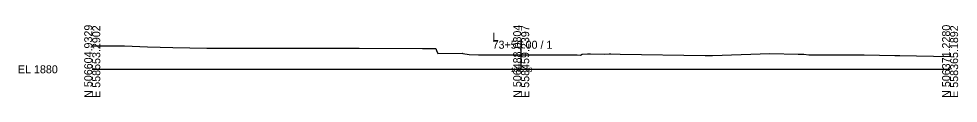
# Model space of a CAD drawing. Extents: x -26 to 4603, y -10 to 4703.
# Drawn here: x 2974.3 to 3302.8, y 1465.3 to 1490.5 of the extents above; entities that cross this region are included whole.
import ezdxf

# ---------------------------------------------------------------- set-up
doc = ezdxf.new("R2010")
doc.units = 0
for name, color, linetype in [('Default', 7, 'Continuous'), ('Exist Cross Section Cell', 7, 'Continuous'), ('Exist XS Ground Line', 7, 'Continuous'), ('Prop XS SS Elevation Text', 7, 'Continuous')]:
    doc.layers.add(name, color=color, linetype=linetype)

msp = doc.modelspace()

# ---------------------------------------------------------------- linework, layer by layer
at = {"layer": 'Exist Cross Section Cell'}
for p, q in [((3150, 1475), (3150, 1485)), ((3000, 1475), (3150, 1475)), ((3150, 1475), (3300, 1475))]:
    msp.add_line(p, q, dxfattribs=at)
at = {"layer": 'Exist XS Ground Line'}
msp.add_lwpolyline([(3000, 1483.22), (3004.2, 1483.2), (3005.44, 1483.22), (3006.64, 1483.24), (3011.24, 1483.24), (3019.32, 1482.86), (3028.16, 1482.58), (3040.09, 1482.43), (3055.6, 1482.39), (3055.71, 1482.39), (3055.81, 1482.39), (3071.23, 1482.42), (3081.91, 1482.42), (3088.69, 1482.34), (3093.31, 1482.38), (3115.45, 1482.32), (3118.49, 1482.32), (3119.25, 1482.29), (3120.16, 1482.31), (3120.43, 1481.63), (3120.85, 1480.5), (3129.34, 1480.62), (3129.58, 1480.58), (3131.79, 1480.18), (3135.09, 1480.08), (3169.36, 1480.07), (3169.57, 1480.02), (3170.73, 1479.9), (3171.33, 1480.27), (3171.38, 1480.33), (3173.19, 1480.42), (3173.46, 1480.42), (3174.24, 1480.42), (3179.3, 1480.34), (3180.83, 1480.38), (3181.05, 1480.38), (3181.34, 1480.39), (3184.59, 1480.34), (3214.4, 1479.78), (3215.62, 1479.82), (3216.91, 1479.79), (3236.96, 1480.58), (3246.85, 1480.32), (3248.88, 1480.26), (3250.57, 1480.01), (3269.97, 1480.05), (3280.63, 1479.84), (3282.42, 1479.81), (3300, 1479.42)], dxfattribs=at)

# ---------------------------------------------------------------- texts
at = {"layer": 'Default'}
msp.add_text('-', height=0.0001, dxfattribs=at).set_placement((3000, 1475))
at = {"layer": 'Exist Cross Section Cell'}
for s, p in [('N 506604.9329', (3000, 1465)), ('E 558553.2902', (3002.8, 1465)), ('N 506488.0804', (3150, 1465)), ('E 558459.2397', (3152.8, 1465)), ('N 506371.2280', (3300, 1465)), ('E 558365.1892', (3302.8, 1465))]:
    msp.add_text(s, height=2.8, rotation=90, dxfattribs=at).set_placement(p)
for s, p in [('73+50.00 / 1', (3140, 1482.2)), ('L', (3140, 1485)), ('EL 1880', (2974, 1473.6))]:
    msp.add_text(s, height=2.8, dxfattribs=at).set_placement(p)
at = {"layer": 'Prop XS SS Elevation Text'}
msp.add_text('1885.08', height=1.5, dxfattribs=at).set_placement((3146.38, 1474.1))

doc.saveas('drawing.dxf')
